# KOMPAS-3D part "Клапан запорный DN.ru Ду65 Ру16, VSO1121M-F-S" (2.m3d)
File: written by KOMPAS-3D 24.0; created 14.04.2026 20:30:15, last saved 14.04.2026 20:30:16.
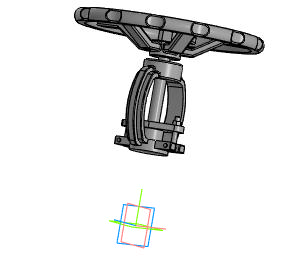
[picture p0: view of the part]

Document properties: Автор: R2D2; Полное имя файла: E:\Работа\Зайцев\VSO3131M-F-S Клапан запорный DN.ru Ду15-100 Ру40\DN65\исходные материалы\2.m3d

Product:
- Part/product: Клапан запорный DN.ru Ду65 Ру16  | designation VSO1121M-F-S
    Масса: 19.42
    Раздел спецификации: Прочие изделия
    Примечание: D090-01948

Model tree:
1. Операция без истории:1
2. Эскиз:1  (with: Ребро.Операция без истории:1)
3. Элемент вращения:1
     Угол 1 = 360
4. Эскиз:2  (with: Ребро.Операция без истории:1, Вершина.Операция без истории:1)
5. Элемент выдавливания:1
     Расстояние 1 = 34
6. Зеркальный массив:1
7. Экземпляр ( 1 )
8. Экземпляр ( 2 )  (with: Элемент выдавливания:1)

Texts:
  VSO1121M-F-S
